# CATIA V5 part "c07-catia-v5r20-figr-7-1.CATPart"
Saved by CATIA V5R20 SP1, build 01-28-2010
Part number: Part1
Bounding box of the stored display mesh (mm): x -50 to 50, y -75 to 75, z 0 to 10
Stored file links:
  D:\v5_r20\psrt_files_downloaded\c07-catia-v5r20-prt\c07-catia-v5r20-figr-7-1.CATPart
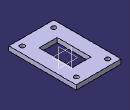
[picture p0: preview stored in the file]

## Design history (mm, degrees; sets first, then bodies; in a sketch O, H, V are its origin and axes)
Body1 (main body)
  Sketch1 on xy-plane, origin (0, 0, 0), H (1, 0, 0), V (0, 1, 0)
    line L1 (-50, 75) -> (50, 75)
    line L2 (50, 75) -> (50, -75)
    line L3 (50, -75) -> (-50, -75)
    line L4 (-50, -75) -> (-50, 75)
    axis line L5 (50, -75) -> (-50, 75)
    length L3 = 100
    length L2 = 150
    horizontal: L1 H, L3 H
    vertical: L2 V, L4 V
    midpoint: O L5
  Pad1: profile Sketch1, direction (0, 0, 1), length 10
  Sketch2 on face of Pad1, origin (0, 0, 10), H (1, 0, 0), V (0, 1, 0)
    line L1 (-20, 37.5) -> (20, 37.5)
    line L2 (20, 37.5) -> (20, -37.5)
    line L3 (20, -37.5) -> (-20, -37.5)
    line L4 (-20, -37.5) -> (-20, 37.5)
    axis line L5 (20, -37.5) -> (-20, 37.5)
    length L3 = 40
    length L2 = 75
    horizontal: L1 H, L3 H
    vertical: L2 V, L4 V
    midpoint: O L5
  Pocket1: profile Sketch2, direction (0, 0, -1), through (limit type 3)
  Sketch3 on face of Pad1, origin (-33.8832, 14.5619, 10), H (1, 0, 0), V (0, 1, 0)
    point P1 (68.8832, -74.5619)
    reference projected line E1 (-16.1168, -89.5619) -> (83.8832, -89.5619) from edge [face of Pad1 | face of Pad1]
    reference projected line E2 (83.8832, -89.5619) -> (83.8832, 60.4381) from edge [face of Pad1 | face of Pad1]
    distance P1 E1 = 15
    distance P1 E2 = 15
  Hole1: placed by Sketch3, at (35, -60, 10) direction (0, 0, -1), diameter 10, through (limit type 3)
  RectPattern1: of Hole1, direction 1 instances 2, spacing 70, along edge [face of Pad1 | face of Pad1] reversed, direction 2 instances 2, spacing 120, along edge [face of Pad1 | face of Pad1]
